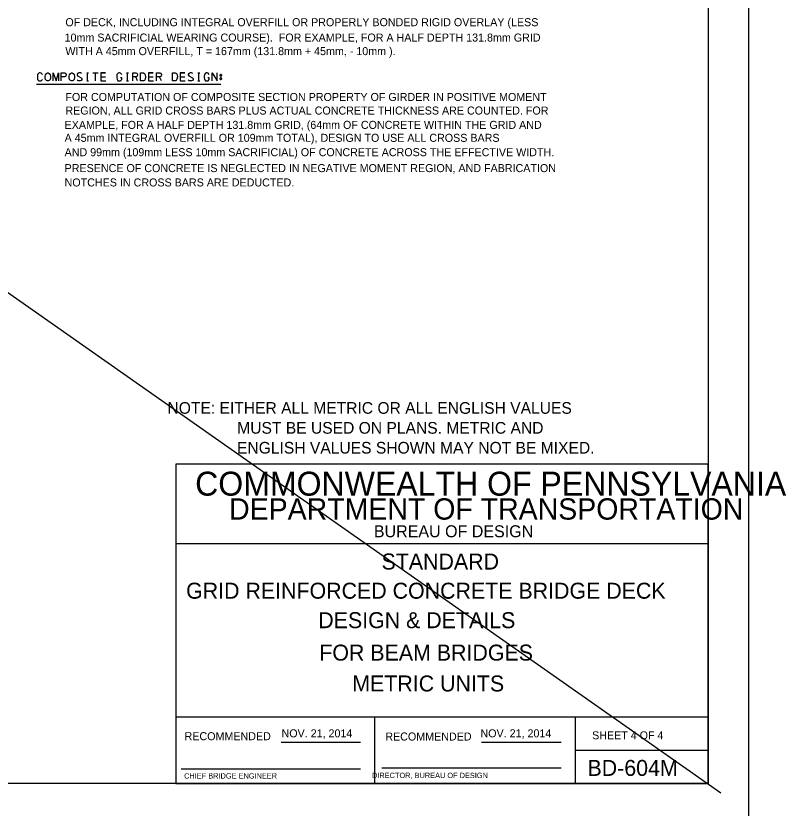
# Model space of a CAD drawing. Extents: x -24512 to -22484, y 4569 to 6351.
# Drawn here: x -22772.2 to -22483.6, y 5762.8 to 6059.6 of the extents above; entities that cross this region are included whole.
import ezdxf

# ---------------------------------------------------------------- set-up
doc = ezdxf.new("R2010")
doc.units = 0
for name, color, linetype in [('10', 7, 'Continuous'), ('2', 7, 'Continuous'), ('40', 7, 'Continuous'), ('6', 7, 'Continuous'), ('PLT-BNDY', 7, 'Continuous')]:
    doc.layers.add(name, color=color, linetype=linetype)

msp = doc.modelspace()

# ---------------------------------------------------------------- linework, layer by layer
at = {"layer": '10'}
msp.add_line((-23319.32, 6337.49), (-22508.07, 5768.63), dxfattribs=at)
at = {"layer": '2'}
for p, q in [((-22512.75, 6334.63), (-22512.75, 5772.04)), ((-22512.75, 5891.74), (-22712.25, 5891.74)), ((-22712.25, 5891.74), (-22712.25, 5772.04)), ((-22512.75, 5772.04), (-22512.75, 5891.74)), ((-22512.75, 5861.82), (-22712.25, 5861.82)), ((-22512.75, 5796.98), (-22712.25, 5796.98)), ((-22637.75, 5772.04), (-22637.75, 5797.04)), ((-22562.63, 5796.98), (-22562.63, 5772.04)), ((-22672.79, 5787.54), (-22643.02, 5787.54)), ((-22597.79, 5787.54), (-22567.88, 5787.54)), ((-22562.63, 5784.51), (-22512.75, 5784.51)), ((-22710.25, 5777.54), (-22643.02, 5777.54)), ((-22635.13, 5777.92), (-22567.88, 5777.92)), ((-22512.75, 5772.04), (-23296.79, 5772.04)), ((-22712.25, 5772.04), (-22512.75, 5772.04))]:
    msp.add_line(p, q, dxfattribs=at)
at = {"layer": '6'}
for points in [[(-22762.27, 6037.66), (-22762.65, 6038.15), (-22763.03, 6038.25), (-22763.29, 6038.25), (-22763.64, 6038.15), (-22764.04, 6037.66), (-22764.14, 6037), (-22764.14, 6036.64), (-22764.14, 6036.41), (-22764.11, 6036.19), (-22764.04, 6035.82), (-22763.64, 6035.34), (-22763.29, 6035.25), (-22763.07, 6035.25), (-22762.67, 6035.34), (-22762.27, 6035.82)], [(-22760.33, 6038.25), (-22760.1, 6038.25), (-22759.7, 6038.08), (-22759.32, 6037.59), (-22759.22, 6037), (-22759.22, 6036.45), (-22759.32, 6035.86), (-22759.72, 6035.37), (-22760.1, 6035.25), (-22760.33, 6035.25), (-22760.69, 6035.37), (-22761.09, 6035.86), (-22761.18, 6036.45), (-22761.18, 6037), (-22761.09, 6037.61), (-22760.69, 6038.11), (-22760.33, 6038.25)], [(-22758.18, 6035.25), (-22758.18, 6038.25), (-22757.15, 6035.25), (-22756.18, 6038.25), (-22756.18, 6035.25)], [(-22755.23, 6035.25), (-22755.23, 6038.25), (-22754.03, 6038.25), (-22753.67, 6038.13), (-22753.37, 6037.66), (-22753.37, 6037.38), (-22753.65, 6036.9), (-22754.03, 6036.78), (-22755.23, 6036.78)], [(-22751.38, 6038.25), (-22751.15, 6038.25), (-22750.74, 6038.08), (-22750.37, 6037.59), (-22750.27, 6037), (-22750.27, 6036.45), (-22750.37, 6035.86), (-22750.77, 6035.37), (-22751.15, 6035.25), (-22751.38, 6035.25), (-22751.74, 6035.37), (-22752.14, 6035.86), (-22752.23, 6036.45), (-22752.23, 6037), (-22752.14, 6037.61), (-22751.74, 6038.11), (-22751.38, 6038.25)], [(-22747.55, 6038.04), (-22748.03, 6038.25), (-22748.57, 6038.25), (-22749.07, 6038.04), (-22749.28, 6037.66), (-22749.28, 6037.52), (-22749.04, 6037.16), (-22747.67, 6036.45), (-22747.44, 6036.12), (-22747.46, 6035.84), (-22747.67, 6035.46), (-22748.07, 6035.25), (-22748.64, 6035.25), (-22748.9, 6035.34), (-22749.28, 6035.6)], [(-22745.64, 6038.25), (-22744.93, 6038.25)], [(-22745.29, 6035.25), (-22745.29, 6038.25)], [(-22743.3, 6038.25), (-22741.32, 6038.25)], [(-22742.31, 6035.25), (-22742.31, 6038.25)], [(-22742.31, 6035.25), (-22742.31, 6038.25)], [(-22738.63, 6038.25), (-22740.35, 6038.25), (-22740.35, 6035.25), (-22738.51, 6035.25)], [(-22740.35, 6038.25), (-22738.63, 6038.25)], [(-22732.53, 6037.66), (-22732.93, 6038.15), (-22733.31, 6038.25), (-22733.59, 6038.25), (-22733.9, 6038.15), (-22734.3, 6037.66), (-22734.4, 6037.02), (-22734.4, 6036.53), (-22734.28, 6035.82), (-22733.93, 6035.34), (-22733.57, 6035.25), (-22733.31, 6035.25), (-22732.93, 6035.34), (-22732.53, 6035.84), (-22732.53, 6036.43), (-22733.05, 6036.43)], [(-22730.76, 6038.25), (-22730.05, 6038.25)], [(-22730.41, 6035.25), (-22730.41, 6038.25)], [(-22728.42, 6035.25), (-22728.42, 6038.25), (-22727.22, 6038.25), (-22726.86, 6038.13), (-22726.56, 6037.66), (-22726.56, 6037.38), (-22726.84, 6036.9), (-22727.22, 6036.78), (-22728.42, 6036.78)], [(-22725.47, 6038.25), (-22724.38, 6038.25), (-22723.98, 6038.04), (-22723.72, 6037.52), (-22723.6, 6036.83), (-22723.74, 6035.98), (-22724, 6035.46), (-22724.38, 6035.25), (-22725.47, 6035.25), (-22725.47, 6038.25)], [(-22720.74, 6038.25), (-22722.47, 6038.25), (-22722.47, 6035.25), (-22720.63, 6035.25)], [(-22722.47, 6038.25), (-22720.74, 6038.25)], [(-22719.52, 6035.25), (-22719.52, 6038.25), (-22718.31, 6038.25), (-22717.96, 6038.13), (-22717.65, 6037.66), (-22717.65, 6037.38), (-22717.93, 6036.9), (-22718.31, 6036.78), (-22719.52, 6036.78)], [(-22713.54, 6038.25), (-22712.45, 6038.25), (-22712.05, 6038.04), (-22711.79, 6037.52), (-22711.67, 6036.83), (-22711.82, 6035.98), (-22712.08, 6035.46), (-22712.45, 6035.25), (-22713.54, 6035.25), (-22713.54, 6038.25)], [(-22708.86, 6038.25), (-22710.59, 6038.25), (-22710.59, 6035.25), (-22708.74, 6035.25)], [(-22710.59, 6038.25), (-22708.86, 6038.25)], [(-22705.86, 6038.04), (-22706.34, 6038.25), (-22706.88, 6038.25), (-22707.37, 6038.04), (-22707.59, 6037.66), (-22707.59, 6037.52), (-22707.35, 6037.16), (-22705.98, 6036.45), (-22705.74, 6036.12), (-22705.77, 6035.84), (-22705.98, 6035.46), (-22706.38, 6035.25), (-22706.95, 6035.25), (-22707.21, 6035.34), (-22707.59, 6035.6)], [(-22703.97, 6038.25), (-22703.26, 6038.25)], [(-22703.62, 6035.25), (-22703.62, 6038.25)], [(-22699.79, 6037.66), (-22700.19, 6038.15), (-22700.57, 6038.25), (-22700.86, 6038.25), (-22701.16, 6038.15), (-22701.56, 6037.66), (-22701.66, 6037.02), (-22701.66, 6036.53), (-22701.54, 6035.82), (-22701.19, 6035.34), (-22700.83, 6035.25), (-22700.57, 6035.25), (-22700.19, 6035.34), (-22699.79, 6035.84), (-22699.79, 6036.43), (-22700.31, 6036.43)], [(-22698.66, 6035.25), (-22698.66, 6038.25), (-22696.79, 6035.25), (-22696.79, 6038.25)], [(-22695.07, 6037.33), (-22695.07, 6037.42), (-22695.09, 6037.52), (-22695.14, 6037.59), (-22695.23, 6037.66), (-22695.33, 6037.71), (-22695.47, 6037.71), (-22695.56, 6037.66), (-22695.66, 6037.56), (-22695.71, 6037.47), (-22695.71, 6037.33), (-22695.66, 6037.21), (-22695.56, 6037.12), (-22695.45, 6037.07), (-22695.33, 6037.07), (-22695.21, 6037.12), (-22695.12, 6037.21), (-22695.07, 6037.33)], [(-22745.64, 6035.25), (-22744.93, 6035.25)], [(-22740.35, 6036.76), (-22738.63, 6036.76)], [(-22740.35, 6036.76), (-22738.63, 6036.76)], [(-22730.76, 6035.25), (-22730.05, 6035.25)], [(-22726.56, 6035.25), (-22727.24, 6036.78)], [(-22722.47, 6036.76), (-22720.74, 6036.76)], [(-22722.47, 6036.76), (-22720.74, 6036.76)], [(-22717.65, 6035.25), (-22718.33, 6036.78)], [(-22710.59, 6036.76), (-22708.86, 6036.76)], [(-22710.59, 6036.76), (-22708.86, 6036.76)], [(-22703.97, 6035.25), (-22703.26, 6035.25)], [(-22695.07, 6036.03), (-22695.07, 6036.12), (-22695.09, 6036.22), (-22695.14, 6036.29), (-22695.23, 6036.36), (-22695.33, 6036.41), (-22695.47, 6036.41), (-22695.56, 6036.36), (-22695.66, 6036.27), (-22695.71, 6036.17), (-22695.71, 6036.03), (-22695.66, 6035.91), (-22695.56, 6035.82), (-22695.45, 6035.77), (-22695.33, 6035.77), (-22695.21, 6035.82), (-22695.12, 6035.91), (-22695.07, 6036.03)], [(-22764.43, 6034.08), (-22695.38, 6034.08)]]:
    msp.add_lwpolyline(points, dxfattribs=at)
at = {"layer": 'PLT-BNDY'}
msp.add_lwpolyline([(-23338.75, 6351.04), (-22497.75, 6351.04), (-22497.75, 5757.04), (-23338.75, 5757.04)], close=True, dxfattribs=at)

# ---------------------------------------------------------------- texts
at = {"layer": '2'}
for s, height, p in [('COMMONWEALTH OF PENNSYLVANIA', 8.9775, (-22705.02, 5879.9)), ('DEPARTMENT OF TRANSPORTATION', 7.9802, (-22692.3, 5870.92)), ('BUREAU OF DESIGN', 4.4888, (-22638.06, 5864.31)), ('STANDARD', 5.985, (-22635.2, 5852.23)), ('GRID REINFORCED CONCRETE BRIDGE DECK', 5.9856, (-22708.41, 5841.3)), ('DESIGN & DETAILS', 5.985, (-22658.89, 5830.26)), ('FOR BEAM BRIDGES', 5.985, (-22658.5, 5818.11)), ('METRIC UNITS', 5.985, (-22646.15, 5806.55)), ('NOV. 21, 2014', 3, (-22672.66, 5789.36)), ('NOV. 21, 2014', 3, (-22598.12, 5789.36)), ('SHEET 4 OF 4', 2.9925, (-22556.27, 5788.63)), ('BD-604M', 5.985, (-22558.02, 5774.91)), ('CHIEF BRIDGE ENGINEER', 2.0002, (-22709.16, 5773.92))]:
    msp.add_text(s, height=height, dxfattribs=at).set_placement(p)
for s, height, p in [('RECOMMENDED', 3, (-22708.98, 5788.29)), ('RECOMMENDED', 3, (-22633.77, 5788.17)), ('   DIRECTOR, BUREAU OF DESIGN', 2.0002, (-22641.06, 5774.1))]:
    msp.add_text(s, height=height, rotation=360, dxfattribs=at).set_placement(p)
at = {"layer": '40'}
for s, p in [('NOTE: EITHER ALL METRIC OR ALL ENGLISH VALUES', (-22715.39, 5910.57)), ('MUST BE USED ON PLANS. METRIC AND', (-22689.26, 5903.11)), ('ENGLISH VALUES SHOWN MAY NOT BE MIXED.', (-22689.33, 5895.66))]:
    msp.add_text(s, height=4.375, dxfattribs=at).set_placement(p)
at = {"layer": '6'}
for s, p in [('OF DECK, INCLUDING INTEGRAL OVERFILL OR PROPERLY BONDED RIGID OVERLAY (LESS ', (-22753.64, 6055.77)), ('10mm SACRIFICIAL WEARING COURSE).  FOR EXAMPLE, FOR A HALF DEPTH 131.8mm GRID ', (-22753.93, 6050.01)), ('WITH A 45mm OVERFILL, T = 167mm (131.8mm + 45mm, - 10mm ).', (-22753.64, 6044.93)), ('FOR COMPUTATION OF COMPOSITE SECTION PROPERTY OF GIRDER IN POSITIVE MOMENT ', (-22753.64, 6027.75)), ('REGION, ALL GRID CROSS BARS PLUS ACTUAL CONCRETE THICKNESS ARE COUNTED. FOR ', (-22753.64, 6022.67)), ('EXAMPLE, FOR A HALF DEPTH 131.8mm GRID, (64mm OF CONCRETE WITHIN THE GRID AND', (-22753.93, 6017.3)), ('A 45mm INTEGRAL OVERFILL OR 109mm TOTAL), DESIGN TO USE ALL CROSS BARS ', (-22753.93, 6012.45)), ('AND 99mm (109mm LESS 10mm SACRIFICIAL) OF CONCRETE ACROSS THE EFFECTIVE WIDTH.', (-22753.93, 6007.07)), ('PRESENCE OF CONCRETE IS NEGLECTED IN NEGATIVE MOMENT REGION, AND FABRICATION', (-22753.93, 6001.11)), ('NOTCHES IN CROSS BARS ARE DEDUCTED.', (-22753.93, 5995.74))]:
    msp.add_text(s, height=2.9999, dxfattribs=at).set_placement(p)

doc.saveas('drawing.dxf')
